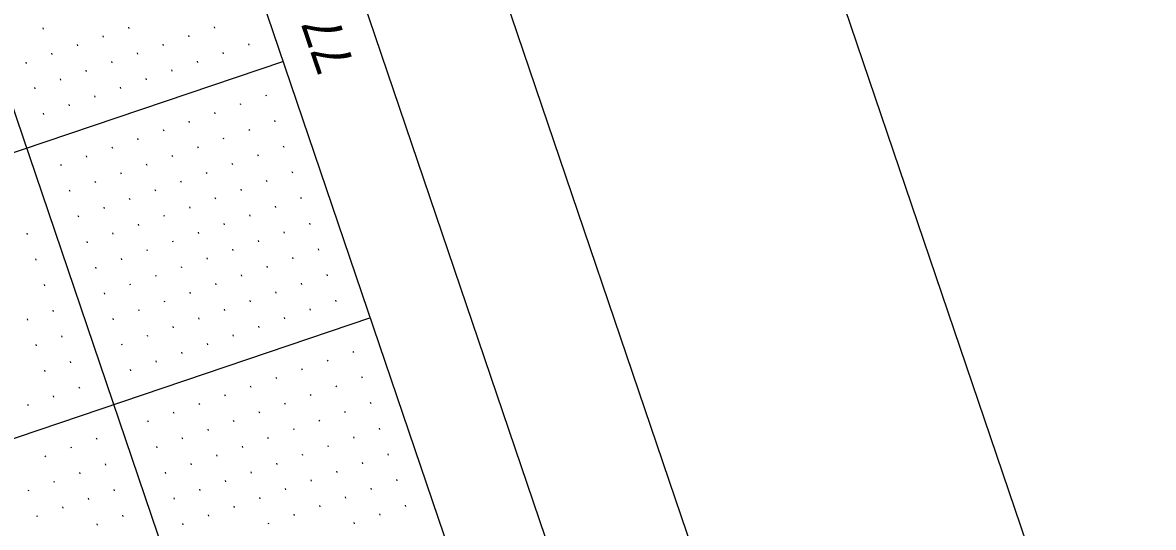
# Model space of a CAD drawing. Extents: x 2150800 to 2152547, y 141860 to 143950.
# Drawn here: x 2152172.8 to 2152381.5, y 142711.2 to 142804.4 of the extents above; entities that cross this region are included whole.
import ezdxf

# ---------------------------------------------------------------- set-up
doc = ezdxf.new("R2010")
doc.units = 0
for name, color, linetype in [('SHT_Plan_Profile_Sheet_Sta_Txt', 7, 'Continuous'), ('SHT_Plot_Shape_Full', 7, 'Continuous'), ('SHT_Plot_Shape_Half', 7, 'Continuous'), ('SHT_Profile_Grid_Major', 7, 'Continuous'), ('SHT_Profile_Grid_Minor', 7, 'Continuous'), ('SHT_Sheet_Border', 7, 'Continuous')]:
    doc.layers.add(name, color=color, linetype=linetype)

msp = doc.modelspace()

# ---------------------------------------------------------------- linework, layer by layer
at = {"layer": 'SHT_Plot_Shape_Full'}
msp.add_lwpolyline([(2151378.63, 141860.13), (2150800.36, 143564.71), (2151936.74, 143950.23), (2152515.02, 142245.65)], close=True, dxfattribs=at)
at = {"layer": 'SHT_Plot_Shape_Half'}
msp.add_lwpolyline([(2151391.39, 141950.92), (2150845.24, 143560.8), (2151886.93, 143914.19), (2152433.08, 142304.31)], close=True, dxfattribs=at)
at = {"layer": 'SHT_Profile_Grid_Major'}
for p, q in [((2152314.16, 142366.92), (2151808.17, 143858.43)), ((2152220.96, 142797.29), (2151747.46, 142636.66)), ((2152237.02, 142749.94), (2151763.75, 142589.39))]:
    msp.add_line(p, q, dxfattribs=at)
at = {"layer": 'SHT_Profile_Grid_Minor'}
for p, q in [((2152176.69, 142803.26), (2152176.61, 142803.5)), ((2152192.5, 142803.35), (2152192.42, 142803.59)), ((2152208.31, 142803.43), (2152208.23, 142803.67)), ((2152183.03, 142800.14), (2152182.95, 142800.37)), ((2152187.77, 142801.74), (2152187.69, 142801.98)), ((2152198.84, 142800.22), (2152198.76, 142800.46)), ((2152203.58, 142801.83), (2152203.5, 142802.06)), ((2152214.65, 142800.3), (2152214.57, 142800.54)), ((2152178.3, 142798.53), (2152178.22, 142798.77)), ((2152194.11, 142798.61), (2152194.03, 142798.85)), ((2152209.92, 142798.7), (2152209.84, 142798.93)), ((2152173.56, 142796.92), (2152173.48, 142797.16)), ((2152189.37, 142797.01), (2152189.29, 142797.24)), ((2152205.18, 142797.09), (2152205.1, 142797.33)), ((2152184.64, 142795.4), (2152184.56, 142795.64)), ((2152195.71, 142793.88), (2152195.63, 142794.12)), ((2152200.45, 142795.48), (2152200.37, 142795.72)), ((2152175.17, 142792.19), (2152175.09, 142792.43)), ((2152179.9, 142793.79), (2152179.82, 142794.03)), ((2152190.98, 142792.27), (2152190.9, 142792.51)), ((2152186.25, 142790.67), (2152186.16, 142790.9)), ((2152217.87, 142790.83), (2152217.79, 142791.07)), ((2152181.51, 142789.06), (2152181.43, 142789.3)), ((2152208.4, 142787.62), (2152208.32, 142787.86)), ((2152213.13, 142789.23), (2152213.05, 142789.46)), ((2152176.78, 142787.45), (2152176.69, 142787.69)), ((2152203.66, 142786.01), (2152203.58, 142786.25)), ((2152219.47, 142786.1), (2152219.39, 142786.34)), ((2152198.93, 142784.41), (2152198.85, 142784.65)), ((2152214.74, 142784.49), (2152214.66, 142784.73)), ((2152194.19, 142782.8), (2152194.11, 142783.04)), ((2152210, 142782.89), (2152209.92, 142783.12)), ((2152221.08, 142781.36), (2152221, 142781.6)), ((2152184.72, 142779.59), (2152184.64, 142779.83)), ((2152189.46, 142781.2), (2152189.38, 142781.43)), ((2152200.53, 142779.67), (2152200.45, 142779.91)), ((2152205.27, 142781.28), (2152205.19, 142781.52)), ((2152216.35, 142779.76), (2152216.26, 142779.99)), ((2152179.99, 142777.98), (2152179.91, 142778.22)), ((2152195.8, 142778.07), (2152195.72, 142778.3)), ((2152211.61, 142778.15), (2152211.53, 142778.39)), ((2152191.06, 142776.46), (2152190.98, 142776.7)), ((2152206.88, 142776.55), (2152206.79, 142776.78)), ((2152222.69, 142776.63), (2152222.61, 142776.87)), ((2152181.59, 142773.25), (2152181.51, 142773.49)), ((2152186.33, 142774.85), (2152186.25, 142775.09)), ((2152197.41, 142773.33), (2152197.32, 142773.57)), ((2152202.14, 142774.94), (2152202.06, 142775.18)), ((2152213.22, 142773.42), (2152213.14, 142773.65)), ((2152217.95, 142775.02), (2152217.87, 142775.26)), ((2152192.67, 142771.73), (2152192.59, 142771.96)), ((2152208.48, 142771.81), (2152208.4, 142772.05)), ((2152224.29, 142771.89), (2152224.21, 142772.13)), ((2152187.94, 142770.12), (2152187.86, 142770.36)), ((2152203.75, 142770.2), (2152203.67, 142770.44)), ((2152219.56, 142770.29), (2152219.48, 142770.52)), ((2152183.2, 142768.51), (2152183.12, 142768.75)), ((2152194.28, 142766.99), (2152194.2, 142767.23)), ((2152199.01, 142768.6), (2152198.93, 142768.83)), ((2152210.09, 142767.08), (2152210.01, 142767.31)), ((2152214.82, 142768.68), (2152214.74, 142768.92)), ((2152225.9, 142767.16), (2152225.82, 142767.4)), ((2152173.73, 142765.3), (2152173.65, 142765.54)), ((2152189.54, 142765.38), (2152189.46, 142765.62)), ((2152205.35, 142765.47), (2152205.27, 142765.71)), ((2152221.16, 142765.55), (2152221.08, 142765.79)), ((2152184.81, 142763.78), (2152184.73, 142764.02)), ((2152200.62, 142763.86), (2152200.54, 142764.1)), ((2152216.43, 142763.95), (2152216.35, 142764.18)), ((2152175.34, 142760.57), (2152175.26, 142760.8)), ((2152191.15, 142760.65), (2152191.07, 142760.89)), ((2152195.88, 142762.26), (2152195.8, 142762.49)), ((2152206.96, 142760.73), (2152206.88, 142760.97)), ((2152211.69, 142762.34), (2152211.61, 142762.58)), ((2152222.77, 142760.82), (2152222.69, 142761.05)), ((2152227.51, 142762.42), (2152227.42, 142762.66)), ((2152186.41, 142759.04), (2152186.33, 142759.28)), ((2152202.22, 142759.13), (2152202.14, 142759.36)), ((2152218.04, 142759.21), (2152217.96, 142759.45)), ((2152197.49, 142757.52), (2152197.41, 142757.76)), ((2152213.3, 142757.61), (2152213.22, 142757.84)), ((2152229.11, 142757.69), (2152229.03, 142757.93)), ((2152176.94, 142755.83), (2152176.86, 142756.07)), ((2152188.02, 142754.31), (2152187.94, 142754.55)), ((2152192.75, 142755.92), (2152192.67, 142756.15)), ((2152203.83, 142754.39), (2152203.75, 142754.63)), ((2152208.57, 142756), (2152208.49, 142756.24)), ((2152219.64, 142754.48), (2152219.56, 142754.71)), ((2152224.38, 142756.08), (2152224.3, 142756.32)), ((2152199.1, 142752.79), (2152199.02, 142753.02)), ((2152214.91, 142752.87), (2152214.83, 142753.11)), ((2152230.72, 142752.95), (2152230.64, 142753.19)), ((2152178.55, 142751.1), (2152178.47, 142751.33)), ((2152194.36, 142751.18), (2152194.28, 142751.42)), ((2152210.17, 142751.26), (2152210.09, 142751.5)), ((2152225.98, 142751.35), (2152225.9, 142751.58)), ((2152173.81, 142749.49), (2152173.73, 142749.73)), ((2152189.63, 142749.57), (2152189.55, 142749.81)), ((2152200.7, 142748.05), (2152200.62, 142748.29)), ((2152205.44, 142749.66), (2152205.36, 142749.89)), ((2152216.51, 142748.14), (2152216.43, 142748.37)), ((2152221.25, 142749.74), (2152221.17, 142749.98)), ((2152180.16, 142746.36), (2152180.08, 142746.6)), ((2152195.97, 142746.45), (2152195.89, 142746.68)), ((2152211.78, 142746.53), (2152211.7, 142746.77)), ((2152175.42, 142744.75), (2152175.34, 142744.99)), ((2152191.23, 142744.84), (2152191.15, 142745.08)), ((2152207.04, 142744.92), (2152206.96, 142745.16)), ((2152197.57, 142741.71), (2152197.49, 142741.95)), ((2152202.31, 142743.32), (2152202.23, 142743.55)), ((2152229.2, 142741.88), (2152229.12, 142742.11)), ((2152233.93, 142743.48), (2152233.85, 142743.72)), ((2152177.03, 142740.02), (2152176.95, 142740.26)), ((2152181.76, 142741.63), (2152181.68, 142741.86)), ((2152192.84, 142740.1), (2152192.76, 142740.34)), ((2152224.46, 142740.27), (2152224.38, 142740.51)), ((2152219.73, 142738.67), (2152219.65, 142738.9)), ((2152235.54, 142738.75), (2152235.46, 142738.99)), ((2152183.37, 142736.89), (2152183.29, 142737.13)), ((2152210.26, 142735.45), (2152210.18, 142735.69)), ((2152214.99, 142737.06), (2152214.91, 142737.3)), ((2152226.07, 142735.54), (2152225.99, 142735.77)), ((2152230.8, 142737.14), (2152230.72, 142737.38)), ((2152173.9, 142733.68), (2152173.82, 142733.92)), ((2152178.63, 142735.28), (2152178.55, 142735.52)), ((2152205.52, 142733.85), (2152205.44, 142734.08)), ((2152221.33, 142733.93), (2152221.25, 142734.17)), ((2152237.14, 142734.01), (2152237.06, 142734.25)), ((2152200.79, 142732.24), (2152200.71, 142732.48)), ((2152216.6, 142732.32), (2152216.52, 142732.56)), ((2152232.41, 142732.41), (2152232.33, 142732.64)), ((2152196.05, 142730.63), (2152195.97, 142730.87)), ((2152211.86, 142730.72), (2152211.78, 142730.95)), ((2152222.94, 142729.2), (2152222.86, 142729.43)), ((2152227.67, 142730.8), (2152227.59, 142731.04)), ((2152238.75, 142729.28), (2152238.67, 142729.52)), ((2152186.58, 142727.42), (2152186.5, 142727.66)), ((2152202.39, 142727.51), (2152202.31, 142727.74)), ((2152207.13, 142729.11), (2152207.05, 142729.35)), ((2152218.2, 142727.59), (2152218.12, 142727.83)), ((2152234.01, 142727.67), (2152233.93, 142727.91)), ((2152181.85, 142725.81), (2152181.77, 142726.05)), ((2152197.66, 142725.9), (2152197.58, 142726.14)), ((2152213.47, 142725.98), (2152213.39, 142726.22)), ((2152229.28, 142726.07), (2152229.2, 142726.3)), ((2152177.11, 142724.21), (2152177.03, 142724.45)), ((2152208.73, 142724.38), (2152208.65, 142724.61)), ((2152224.54, 142724.46), (2152224.46, 142724.7)), ((2152235.62, 142722.94), (2152235.54, 142723.18)), ((2152240.36, 142724.54), (2152240.28, 142724.78)), ((2152183.45, 142721.08), (2152183.37, 142721.32)), ((2152188.19, 142722.69), (2152188.11, 142722.92)), ((2152199.26, 142721.16), (2152199.18, 142721.4)), ((2152204, 142722.77), (2152203.92, 142723.01)), ((2152215.07, 142721.25), (2152214.99, 142721.48)), ((2152219.81, 142722.85), (2152219.73, 142723.09)), ((2152230.89, 142721.33), (2152230.81, 142721.57)), ((2152178.72, 142719.47), (2152178.64, 142719.71)), ((2152210.34, 142719.64), (2152210.26, 142719.88)), ((2152226.15, 142719.73), (2152226.07, 142719.96)), ((2152241.96, 142719.81), (2152241.88, 142720.05)), ((2152173.98, 142717.87), (2152173.9, 142718.1)), ((2152189.79, 142717.95), (2152189.71, 142718.19)), ((2152205.6, 142718.04), (2152205.52, 142718.27)), ((2152221.42, 142718.12), (2152221.34, 142718.36)), ((2152237.23, 142718.2), (2152237.15, 142718.44)), ((2152180.32, 142714.74), (2152180.24, 142714.98)), ((2152185.06, 142716.35), (2152184.98, 142716.58)), ((2152200.87, 142716.43), (2152200.79, 142716.67)), ((2152211.95, 142714.91), (2152211.87, 142715.14)), ((2152216.68, 142716.51), (2152216.6, 142716.75)), ((2152227.76, 142714.99), (2152227.68, 142715.23)), ((2152232.49, 142716.6), (2152232.41, 142716.83)), ((2152243.57, 142715.07), (2152243.49, 142715.31)), ((2152175.59, 142713.13), (2152175.51, 142713.37)), ((2152191.4, 142713.22), (2152191.32, 142713.45)), ((2152207.21, 142713.3), (2152207.13, 142713.54)), ((2152223.02, 142713.38), (2152222.94, 142713.62)), ((2152238.83, 142713.47), (2152238.75, 142713.71)), ((2152186.67, 142711.61), (2152186.58, 142711.85)), ((2152202.48, 142711.69), (2152202.4, 142711.93)), ((2152218.29, 142711.78), (2152218.21, 142712.01)), ((2152234.1, 142711.86), (2152234.02, 142712.1))]:
    msp.add_line(p, q, dxfattribs=at)
at = {"layer": 'SHT_Sheet_Border'}
msp.add_line((2152361.51, 142382.99), (2151939.85, 143625.91), dxfattribs=at)
msp.add_lwpolyline([(2151383.74, 142051.28), (2150877.75, 143542.79), (2151872.09, 143880.12), (2152378.08, 142388.61)], close=True, dxfattribs=at)

# ---------------------------------------------------------------- texts
at = {"layer": 'SHT_Plan_Profile_Sheet_Sta_Txt'}
msp.add_text('77', height=7, rotation=108.7393, dxfattribs=at).set_placement((2152234.12, 142796.62))

doc.saveas('drawing.dxf')
